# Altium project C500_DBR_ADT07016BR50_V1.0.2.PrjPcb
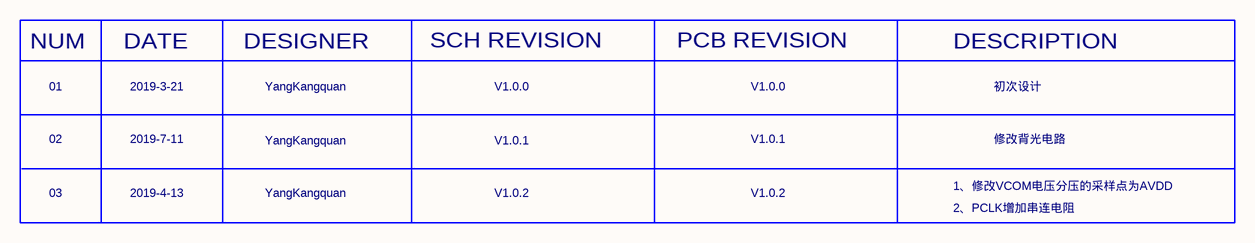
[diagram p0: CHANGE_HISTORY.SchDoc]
3 sheets, 129 parts. Net scope: flat (ports and power ports of the same name join across sheets).
Sheets:
  CHANGE_HISTORY.SchDoc
  POWER.SchDoc
  CONNECT.SchDoc

## Sheet CHANGE_HISTORY.SchDoc: C500_DBR_ADT07016BR50
size A3; Revision: V1.0.2; SheetNumber: 1; SheetTotal: 3

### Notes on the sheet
- NUM
- DATE
- DESIGNER
- SCH REVISION
- PCB REVISION
- DESCRIPTION
- 01
- 2019-3-21
- YangKangquan
- V1.0.0
- 初次设计
- 02
- 03
- 2019-7-11
- 2019-4-13
- V1.0.1
- V1.0.2
- 1、修改VCOM电压分压的采样点为AVDD
- 修改背光电路
- 2、PCLK增加串连电阻

## Sheet POWER.SchDoc: C500_DBR_ADT07016BR50
size A3; Revision: V1.0.2; SheetNumber: 2; SheetTotal: 3
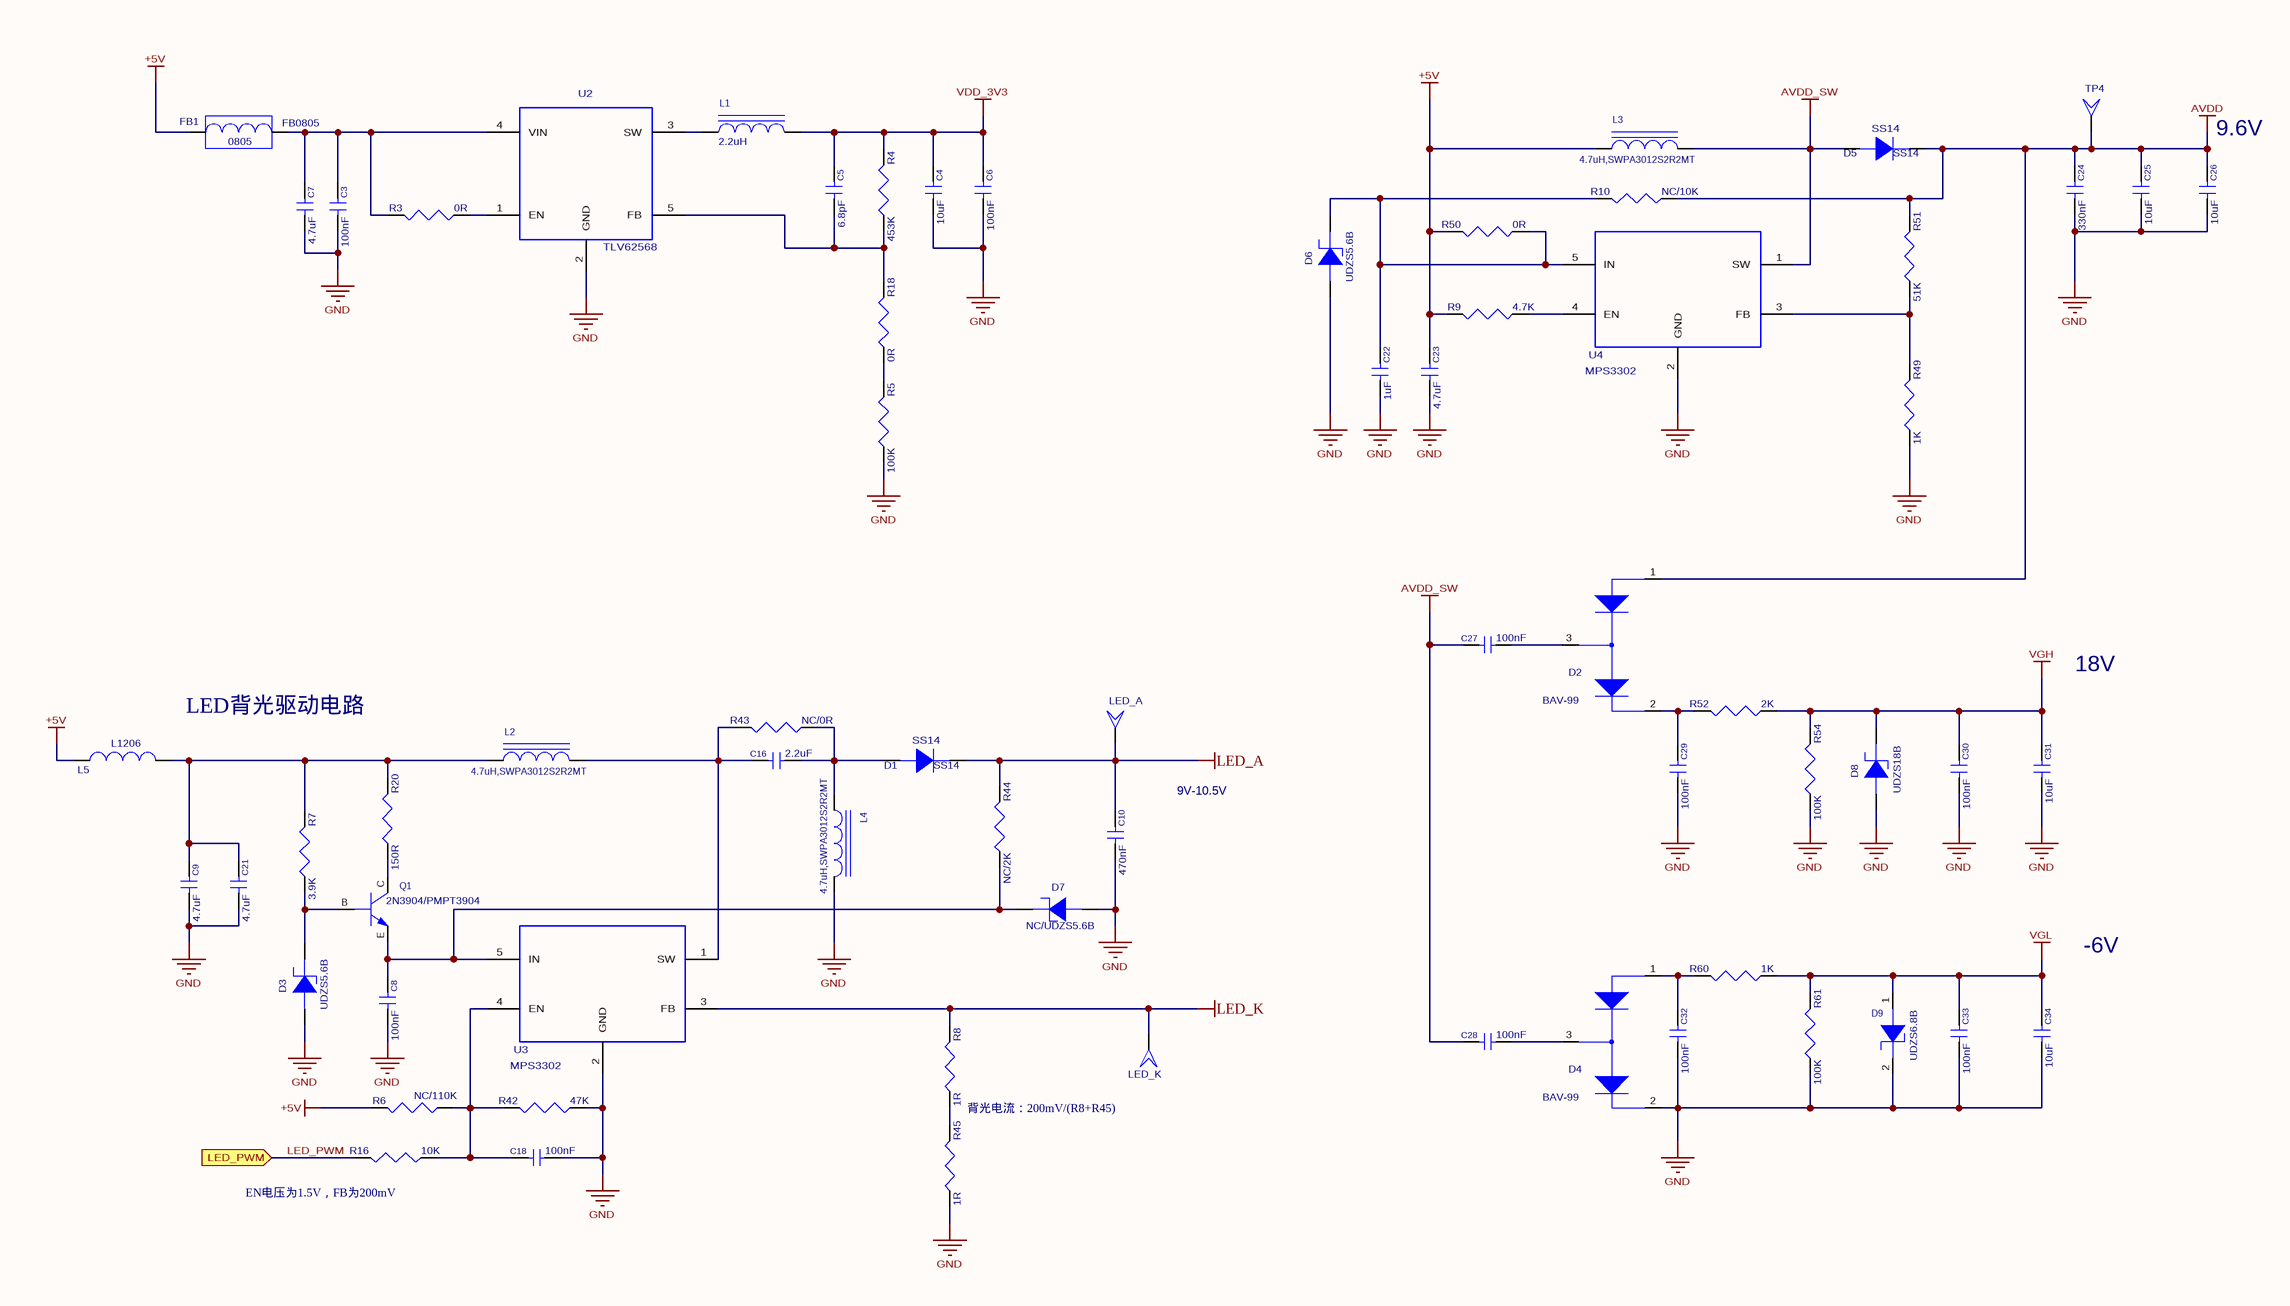
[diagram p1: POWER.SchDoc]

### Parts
C3  100nF  [C0603]
C4  10uF  [C0603]
C5  6.8pF  [C0603]
C6  100nF  [C0603]
C7  4.7uF  [C0603]
C8  100nF  [C0603]
C9  4.7uF  [C0603]
C10  470nF  [C0603]
C16  2.2uF  [C0603]
C18  100nF  [C0603]
C21  4.7uF  [C0603]
C22  1uF  [C0603]
C23  4.7uF  [C0603]
C24  330nF  [C0603]
C25  10uF  [C0603]
C26  10uF  [C0603]
C27  100nF  [C0603]
C28  100nF  [C0603]
C29  100nF  [C0603]
C30  100nF  [C0603]
C31  10uF  [C0603]
C32  100nF  [C0603]
C33  100nF  [C0603]
C34  10uF  [C0603]
D1  SS14  [SS14]
D2  BAV-99  [BAV-99_SOT23_123]
D3  UDZS5.6B  [UDZS6.8B]
D4  BAV-99  [BAV-99_SOT23_123]
D5  SS14  [SS14]
D6  UDZS5.6B  [UDZS6.8B]
D7  NC/UDZS5.6B  [UDZS6.8B]
D8  UDZS18B  [UDZS6.8B]
D9  UDZS6.8B  [UDZS6.8B]
FB1  FB0805  [FB0805]
L1  2.2uH  [L_SWPA3012_3X3MM]
L2  value 4.7uH,SWPA3012S2R2MT  [L_SWPA3012_3X3MM]  (hidden comment: 4.7uH,SWPA3012S4R7MT)
L3  value 4.7uH,SWPA3012S2R2MT  [L_SWPA3012_3X3MM]  (hidden comment: 4.7uH,SWPA3012S4R7MT)
L4  value 4.7uH,SWPA3012S2R2MT  [L_SWPA3012_3X3MM]  (hidden comment: 4.7uH,SWPA3012S4R7MT)
L5  L1206  [L1206]
LED_A  TP40  [TP40]  (value not drawn)
LED_K  TP40  [TP40]  (value not drawn)
Q1  value 2N3904/PMPT3904  [2N3904/PMBT3904]  (hidden comment: 2N3904/PMBT3904)
R3  0R  [R0603]
R4  453K  [R0603]
R5  100K  [R0603]
R6  NC/110K  [R0603]
R7  3.9K  [R0603]
R8  1R  [R0603]
R9  4.7K  [R0603]
R10  NC/10K  [R0603]
R16  10K  [R0603]
R18  0R  [R0603]
R20  150R  [R0603]
R42  47K  [R0603]
R43  NC/0R  [R0603]
R44  NC/2K  [R0603]
R45  1R  [R0603]
R49  1K  [R0603]
R50  0R  [R0603]
R51  51K  [R0603]
R52  2K  [R0603]
R54  100K  [R0603]
R60  1K  [R0603]
R61  100K  [R0603]
TP4  TP40  [TP40]  (value not drawn)
U2  TLV62568  [PAM2312_SOT23_5]
U3  MPS3302  [MPS3302_SOT23-5]
U4  MPS3302  [MPS3302_SOT23-5]

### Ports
LED_PWM (in)

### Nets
+5V: C23.1 FB1.1 L3.1 L5.1 R6.2 R9.2 R50.2
AVDD: C24.1 C25.1 C26.1 D2.1(GND) D5.K R10.1 R51.2 TP4.1
AVDD_SW: C27.1 C28.1 D5.A L3.2 U4.1(SW)
GND: C3.2 C4.2 C6.2 C7.2 C8.2 C9.2 C10.2 C18.2 C21.2 C22.2 C23.2 C24.2 C25.2 C26.2 C29.2 C30.2 C31.2 C32.2 C33.2 C34.2 D3.1(A) D4.2(VDD) D6.1(A) D7.1(A) D8.1(A) D9.2(K) L4.2 R5.1 R42.1 R45.1 R49.1 R54.1 R61.1 U2.2(GND) U3.2(GND) U4.2(GND)
LED_A: C10.1 D1.K LED_A.1 R44.2
LED_K: LED_K.1 R8.2 U3.3(FB)
VDD_3V3: C4.1 C5.1 C6.1 L1.2 R4.2
VGH: C30.1 C31.1 D8.2(K) R52.1 R54.2
VGL: C33.1 C34.1 D9.1(A) R60.1 R61.2
LED_PWM: R16.2 ; port LED_PWM
NetC3_1: C3.1 C7.1 FB1.2 R3.2 U2.4(VIN)
NetC5_2: C5.2 R4.1 R18.2 U2.5(FB)
NetC8_1: C8.1 D7.2(K) Q1.E R44.1 U3.5(IN)
NetC9_1: C9.1 C21.1 L2.1 L5.2 R7.2 R20.2
NetC16_1: C16.1 L2.2 R43.2 U3.1(SW)
NetC16_2: C16.2 D1.A L4.1 R43.1
NetC18_1: C18.1 R6.1 R16.1 R42.2 U3.4(EN)
NetC22_1: C22.1 D6.2(K) R10.2 R50.1 U4.5(IN)
NetC27_2: C27.2 D2.3(SIGNAL)
NetC28_2: C28.2 D4.3(SIGNAL)
NetC29_1: C29.1 D2.2(VDD) R52.2
NetC32_1: C32.1 D4.1(GND) R60.2
NetD3_2: D3.2(K) Q1.B R7.1
NetL1_1: L1.1 U2.3(SW)
NetQ1_C: Q1.C R20.1
NetR3_1: R3.1 U2.1(EN)
NetR5_2: R5.2 R18.1
NetR8_1: R8.1 R45.2
NetR9_1: R9.1 U4.4(EN)
NetR49_2: R49.2 R51.1 U4.3(FB)

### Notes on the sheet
- (near C26) 9.6V
- 18V
- (near L5) LED背光驱动电路
- 9V-10.5V
- -6V
- 背光电流：200mV/(R8+R45)
- (near R16) EN电压为1.5V，FB为200mV

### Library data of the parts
C3 C6 C8 C18 C27-C30 C32 C33 = CC0301040XX: C/C,100nF,25V,+/-5%,0603; Catalog: 陶瓷电容
C4 = CC0301064XX: C/C,10uF,6.3V,+/-20%,0603; Catalog: 陶瓷电容
C5 = CC0306R80XX: C/C,6.8pF,50V,+/-0.25pF,0603; Catalog: 陶瓷电容
C7 C9 C21 C23 = CC0304752XX: C/C,4.7uF,10V +/-10%,0603; Catalog: 陶瓷电容
C10 = CC0304742XX: C/C,470nF,25V,+/-10%,0603; Catalog: 陶瓷电容
C16 = CC0302251XX: C/C,2.2uF,25V,+/-5%,,0603; Catalog: 陶瓷电容
C22 = CC0301055XX: C/C,1uF,16V,+/-10%,0603; Catalog: 陶瓷电容
C24 = CC0303340XX: C/C,330nF,50V,+/-5%,0603; Catalog: 陶瓷电容
C25 C26 C31 C34 = CC0301060XX: C/C,10uF,25V,+/-5%,0603; Catalog: 陶瓷电容
D1 D5 = DDD0SCH00XX: SS14 DO-214AC 肖特基二极管; Catalog: 二极管
D2 D4 = DD21SSD00XX: Small signal Diodes,onsemi,BAV99LT1G,SOT23; Catalog: 二极管
D3 D6 = DD23ZEN03XX: Zener Diode,UDZS5.6B,5.6V,S0D-323; Catalog: 二极管
D7 = DD23ZEN03XX: Zener Diode,UDZS5.6B,5.6V,S0D-323; Remark: NC; Catalog: 二极管
D8 = DD23ZEN04XX: 稳压管：Zener Diode,UDZS18B,18V,S0D-323; PCB DECAL: UDZS5.6B; Catalog: 二极管
D9 = DD33ZEN68XX: Zener Diode,UDZS6.8B,6.8V,S0D-323; Catalog: 稳压管
FB1 = BE0503010XX: BEAD,PZ2012U301-1R5TF,300R,100MHz,0805; Catalog: 贴片磁珠
L1 = WL1C02R20XX: 2.2uH,SWPA3012S2R2NT; SOURCE_PATH: E:\工作目录\ORCAD原理图库\ORCAD元件库\磁珠&电感.OLB; Catalog: 贴片电感
L2-L4 = WL1C04R70XX: Part Number_AK: WL1C02R20XX; SOURCE_PATH: E:\工作目录\ORCAD原理图库\ORCAD元件库\磁珠&电感.OLB; Catalog: 贴片电感
L5 = BE0606010XX: PZ3216D601_L1206,PZ3216D601-1R5TF; SOURCE_PATH: E:\工作目录\ORCAD原理图库\ORCAD元件库\磁珠&电感.OLB; Catalog: 贴片磁珠
Q1 = TR05NGN00XX: 2N3904/PMBT3904,SOT-23,NPN,GP; PCB DECAL: 2N3904/PMBT3904_SOT23_BCE_NPN; Catalog: 三极管
R3 R18 R43 R50 = CR0300000XX: Res,0R,1/10W,+/-5%,0603; Catalog: 贴片电阻
R4 = CR0345330XX: Res,453K,1/16W,+/-1%,0603; Catalog: 贴片电阻
R5 R54 R61 = CR0310030XX: Res,100K,1/10W,+/-1%,0603; Catalog: 贴片电阻
R6 = CR0311030XX: Res,110K,1/10W,+/-1%,0603; Catalog: 贴片电阻
R7 = CR0339010XX: Res,3.9K,1/10W,+/-1%,0603; Catalog: 贴片电阻
R8 R45 = CR031R000XX: Res,1R,1/10W,+/-1%,0603; Catalog: 贴片电阻
R9 = CR0304720XX: Res,4.7K,1/10W,+/-5%,0603; Catalog: 贴片电阻
R10 R16 = CR0310020XX: Res,10K,1/10W,+/-1%,0603; Remark: NC; Catalog: 贴片电阻
R20 = CR0315000XX: Res,150R,1/10W,+/-1%,0603; Catalog: 贴片电阻
R42 = CR0347020XX: Res,47K,1/10W,+/-1%,0603; Catalog: 贴片电阻
R44 R52 = CR0302020XX: Res,2K,1/10W,+/-5%,0603; Catalog: 贴片电阻
R49 R60 = CR0301020XX: Res,1K,1/10W,+/-5%,0603; Catalog: 贴片电阻
R51 = CR0305131XX: Res,51K,1/10W,+/-1%,0603; Catalog: 贴片电阻
U2 = JCSOTPW23XX: PowerIC , TI, TLV62568DBV, SOT23-5; PCB DECAL: TLV62568_SOT23-5; Catalog: 集成电路
U3 U4 = JCSOTDR00XX: IC MP3302，LCD Drives LED，TSOT23-5; Catalog: 集成电路

## Sheet CONNECT.SchDoc: C500_DBR_ADT07016BR50
size A3; Revision: V1.0.2; SheetNumber: 3; SheetTotal: 3
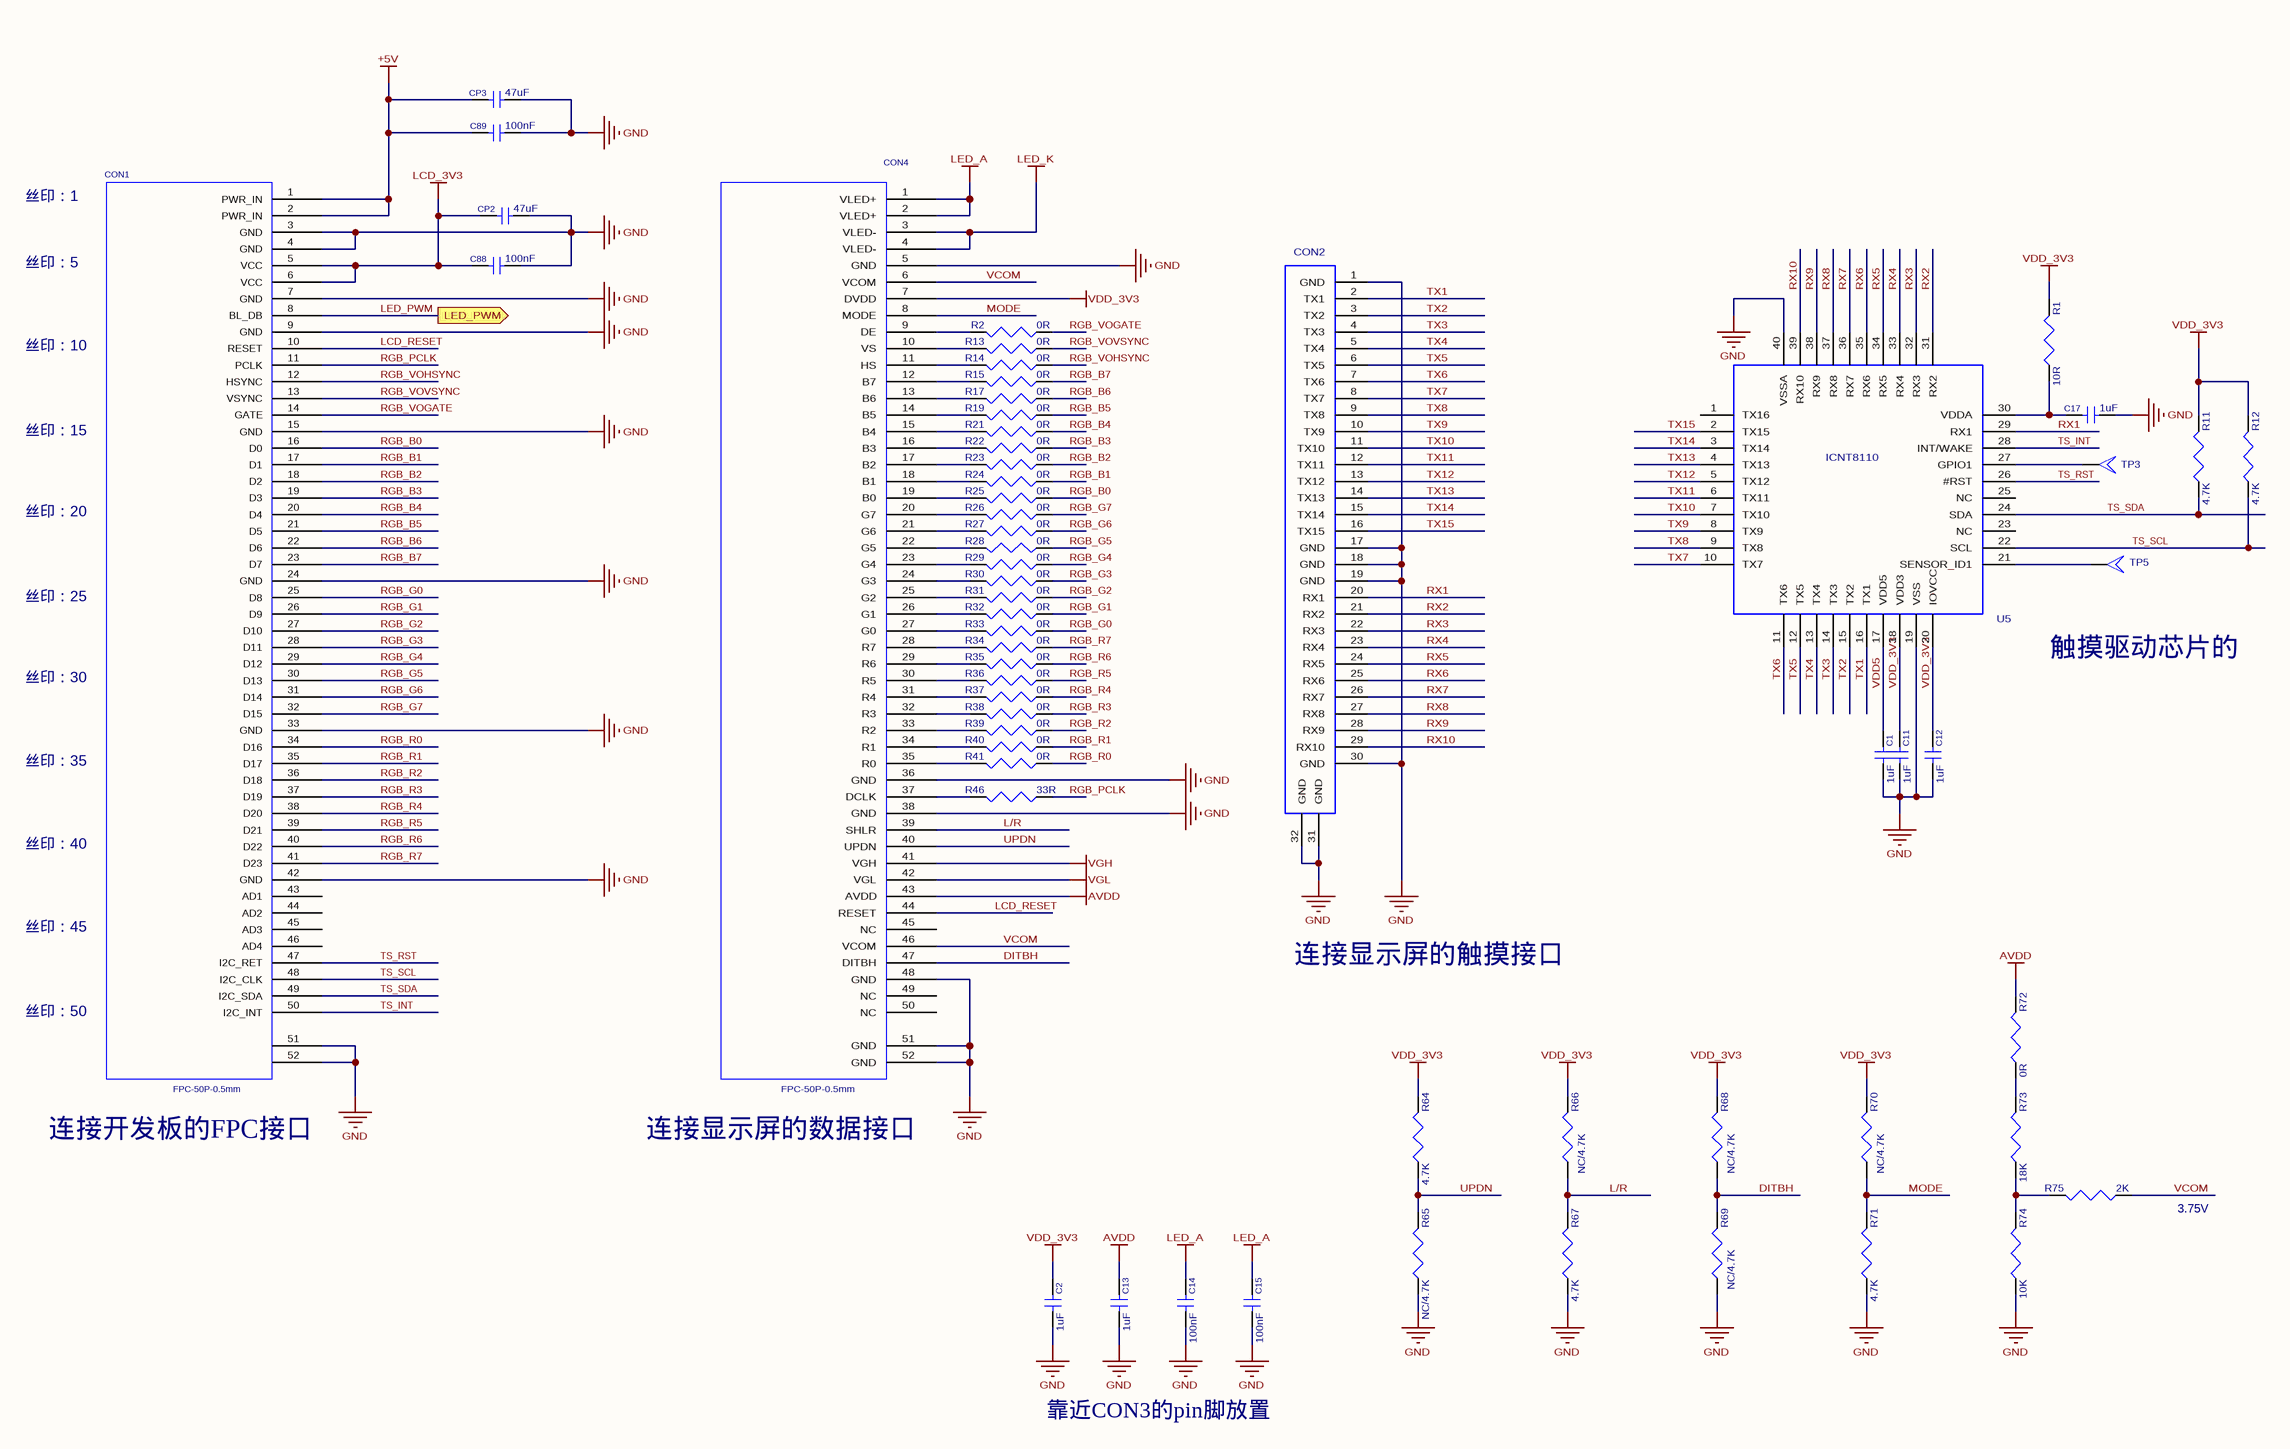
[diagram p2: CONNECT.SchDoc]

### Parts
C1  1uF  [C0603]
C2  1uF  [C0603]
C11  1uF  [C0603]
C12  1uF  [C0603]
C13  1uF  [C0603]
C14  100nF  [C0603]
C15  100nF  [C0603]
C17  1uF  [C0603]
C88  100nF  [C0603]
C89  100nF  [C0603]
CON1  FPC-50P-0.5MM  [FPC-50P-0.5MM]
CON2  CON30_FPC_0.5MM  [CON30_0MM5]  (value not drawn)
CON4  value FPC-50P-0.5mm  [FPC_LCD_50P_0.5mm]  (hidden comment: FPC_LCD_50P_0.5mm)
CP2  47uF  [C1210]
CP3  47uF  [C1210]
R1  10R  [R0603]
R2  0R  [R0603]
R11  4.7K  [R0603]
R12  4.7K  [R0603]
R13  0R  [R0603]
R14  0R  [R0603]
R15  0R  [R0603]
R17  0R  [R0603]
R19  0R  [R0603]
R21  0R  [R0603]
R22  0R  [R0603]
R23  0R  [R0603]
R24  0R  [R0603]
R25  0R  [R0603]
R26  0R  [R0603]
R27  0R  [R0603]
R28  0R  [R0603]
R29  0R  [R0603]
R30  0R  [R0603]
R31  0R  [R0603]
R32  0R  [R0603]
R33  0R  [R0603]
R34  0R  [R0603]
R35  0R  [R0603]
R36  0R  [R0603]
R37  0R  [R0603]
R38  0R  [R0603]
R39  0R  [R0603]
R40  0R  [R0603]
R41  0R  [R0603]
R46  33R  [R0603]
R64  4.7K  [R0603]
R65  NC/4.7K  [R0603]
R66  NC/4.7K  [R0603]
R67  4.7K  [R0603]
R68  NC/4.7K  [R0603]
R69  NC/4.7K  [R0603]
R70  NC/4.7K  [R0603]
R71  4.7K  [R0603]
R72  0R  [R0603]
R73  18K  [R0603]
R74  10K  [R0603]
R75  2K  [R0603]
TP3  TP40  [TP40]  (value not drawn)
TP5  TP40  [TP40]  (value not drawn)
U5  ICNT8110  [QFN40_0MM5_5X5MM]  (value not drawn)

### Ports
LED_PWM (out)

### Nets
+5V: C89.1 CON1.1(PWR_IN) CON1.2(PWR_IN) CP3.1
AVDD: C13.1 CON4.43(AVDD) R72.2
GND: C1.2 C2.2 C11.2 C12.2 C13.2 C14.2 C15.2 C17.2 C88.2 C89.2 CON1.3(GND) CON1.4(GND) CON1.7(GND) CON1.9(GND) CON1.15(GND) CON1.24(GND) CON1.33(GND) CON1.42(GND) CON1.51 CON1.52 CON2.1(GND) CON2.17(GND) CON2.18(GND) CON2.19(GND) CON2.30(GND) CON2.31(GND) CON2.32(GND) CON4.5(GND) CON4.36(GND) CON4.38(GND) CON4.48(GND) CON4.51(GND) CON4.52(GND) CP2.2 CP3.2 R65.1 R67.1 R69.1 R71.1 R74.1 U5.19(VSS) U5.40(VSSA)
LCD_3V3: C88.1 CON1.5(VCC) CON1.6(VCC) CP2.1
LED_A: C14.1 C15.1 CON4.1(VLED+) CON4.2(VLED+)
LED_K: CON4.3(VLED-) CON4.4(VLED-)
VDD_3V3: C2.1 C11.1 C12.1 CON4.7(DVDD) R1.2 R11.2 R12.2 R64.2 R66.2 R68.2 R70.2 U5.18(VDD3) U5.20(IOVCC)
VGH: CON4.41(VGH)
VGL: CON4.42(VGL)
DITBH: CON4.47(DITBH) R68.1 R69.2
L/R: CON4.39(SHLR) R66.1 R67.2
LCD_RESET: CON1.10(RESET) CON4.44(RESET)
LED_PWM: CON1.8(BL_DB) ; port LED_PWM
MODE: CON4.8(MODE) R70.1 R71.2
RGB_B0: CON1.16(D0) R25.1
RGB_B1: CON1.17(D1) R24.1
RGB_B2: CON1.18(D2) R23.1
RGB_B3: CON1.19(D3) R22.1
RGB_B4: CON1.20(D4) R21.1
RGB_B5: CON1.21(D5) R19.1
RGB_B6: CON1.22(D6) R17.1
RGB_B7: CON1.23(D7) R15.1
RGB_G0: CON1.25(D8) R33.1
RGB_G1: CON1.26(D9) R32.1
RGB_G2: CON1.27(D10) R31.1
RGB_G3: CON1.28(D11) R30.1
RGB_G4: CON1.29(D12) R29.1
RGB_G5: CON1.30(D13) R28.1
RGB_G6: CON1.31(D14) R27.1
RGB_G7: CON1.32(D15) R26.1
RGB_PCLK: CON1.11(PCLK) R46.1
RGB_R0: CON1.34(D16) R41.1
RGB_R1: CON1.35(D17) R40.1
RGB_R2: CON1.36(D18) R39.1
RGB_R3: CON1.37(D19) R38.1
RGB_R4: CON1.38(D20) R37.1
RGB_R5: CON1.39(D21) R36.1
RGB_R6: CON1.40(D22) R35.1
RGB_R7: CON1.41(D23) R34.1
RGB_VOGATE: CON1.14(GATE) R2.1
RGB_VOHSYNC: CON1.12(HSYNC) R14.1
RGB_VOVSYNC: CON1.13(VSYNC) R13.1
RX1: CON2.20(RX1) U5.29(RX1)
RX2: CON2.21(RX2) U5.31(RX2)
RX3: CON2.22(RX3) U5.32(RX3)
RX4: CON2.23(RX4) U5.33(RX4)
RX5: CON2.24(RX5) U5.34(RX5)
RX6: CON2.25(RX6) U5.35(RX6)
RX7: CON2.26(RX7) U5.36(RX7)
RX8: CON2.27(RX8) U5.37(RX8)
RX9: CON2.28(RX9) U5.38(RX9)
RX10: CON2.29(RX10) U5.39(RX10)
TS_INT: CON1.50(I2C_INT) U5.28(INT/WAKE)
TS_RST: CON1.47(I2C_RET) U5.26(#RST)
TS_SCL: CON1.48(I2C_CLK) R12.1 U5.22(SCL)
TS_SDA: CON1.49(I2C_SDA) R11.1 U5.24(SDA)
TX1: CON2.2(TX1) U5.16(TX1)
TX2: CON2.3(TX2) U5.15(TX2)
TX3: CON2.4(TX3) U5.14(TX3)
TX4: CON2.5(TX4) U5.13(TX4)
TX5: CON2.6(TX5) U5.12(TX5)
TX6: CON2.7(TX6) U5.11(TX6)
TX7: CON2.8(TX7) U5.10(TX7)
TX8: CON2.9(TX8) U5.9(TX8)
TX9: CON2.10(TX9) U5.8(TX9)
TX10: CON2.11(TX10) U5.7(TX10)
TX11: CON2.12(TX11) U5.6(TX11)
TX12: CON2.13(TX12) U5.5(TX12)
TX13: CON2.14(TX13) U5.4(TX13)
TX14: CON2.15(TX14) U5.3(TX14)
TX15: CON2.16(TX15) U5.2(TX15)
UPDN: CON4.40(UPDN) R64.1 R65.2
VCOM: CON4.6(VCOM) CON4.46(VCOM) R75.1
VDD5: C1.1 U5.17(VDD5)
NetC17_1: C17.1 R1.1 U5.30(VDDA)
NetCON4_9: CON4.9(DE) R2.2
NetCON4_10: CON4.10(VS) R13.2
NetCON4_11: CON4.11(HS) R14.2
NetCON4_12: CON4.12(B7) R15.2
NetCON4_13: CON4.13(B6) R17.2
NetCON4_14: CON4.14(B5) R19.2
NetCON4_15: CON4.15(B4) R21.2
NetCON4_16: CON4.16(B3) R22.2
NetCON4_17: CON4.17(B2) R23.2
NetCON4_18: CON4.18(B1) R24.2
NetCON4_19: CON4.19(B0) R25.2
NetCON4_20: CON4.20(G7) R26.2
NetCON4_21: CON4.21(G6) R27.2
NetCON4_22: CON4.22(G5) R28.2
NetCON4_23: CON4.23(G4) R29.2
NetCON4_24: CON4.24(G3) R30.2
NetCON4_25: CON4.25(G2) R31.2
NetCON4_26: CON4.26(G1) R32.2
NetCON4_27: CON4.27(G0) R33.2
NetCON4_28: CON4.28(R7) R34.2
NetCON4_29: CON4.29(R6) R35.2
NetCON4_30: CON4.30(R5) R36.2
NetCON4_31: CON4.31(R4) R37.2
NetCON4_32: CON4.32(R3) R38.2
NetCON4_33: CON4.33(R2) R39.2
NetCON4_34: CON4.34(R1) R40.2
NetCON4_35: CON4.35(R0) R41.2
NetCON4_37: CON4.37(DCLK) R46.2
NetR72_1: R72.1 R73.2
NetR73_1: R73.1 R74.2 R75.2
NetTP3_1: TP3.1 U5.27(GPIO1)
NetTP5_1: TP5.1 U5.21(SENSOR_ID1)

Not connected (* = marked no-connect by the designer): CON1 43(AD1) 44(AD2) 45(AD3) 46(AD4); CON4 45(NC) 49(NC) 50(NC); U5 1(TX16) 23(NC) 25(NC)

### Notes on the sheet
- 丝印：1
- 丝印：5
- 丝印：10
- 丝印：15
- 丝印：20
- 丝印：25
- 丝印：30
- 触摸驱动芯片的
- 丝印：35
- 丝印：40
- 丝印：45
- 连接显示屏的触摸接口
- 丝印：50
- 连接开发板的FPC接口
- 连接显示屏的数据接口
- (near R75) 3.75V
- 靠近CON3的pin脚放置

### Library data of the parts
C1 C2 C11-C13 C17 = CC0301055XX: C/C,1uF,16V,+/-10%,0603; Catalog: 陶瓷电容
C14 C15 C88 C89 = CC0301040XX: C/C,100nF,25V,+/-5%,0603; Catalog: 陶瓷电容
CON1 = CNFPF5001XX: 连接器 FPC连接器，50P，0.5mm，翻盖式，H=2mm; ROOM: lcd1; Source Path: D:\MAGIC\SCHEMATICS\MAGIC_DAUGHTERBD_EVT_V1.DSN; PCB DECAL: CON50_0MM5; Catalog: Connector
CON2 = CNFPF3002XX: 连接器 FPC连接器 FPC0.5mm -30P H1.0mm 前插后掀；; Catalog: Connector
CON4 = CNFPC5000XX: FPC连接器 FPC0.5mm -50P H1.0mm 前插后掀；; ROOM: lcd1; Source Path: D:\MAGIC\SCHEMATICS\MAGIC_DAUGHTERBD_EVT_V1.DSN; PCB DECAL: SAT070AT50D18Y0_LCD; Catalog: Connector
CP2 CP3 = TC1004761XX: T/C,47uF,10V,+/-10%,1210; Catalog: 陶瓷电容
R1 = CR0301000XX: Res,10R,1/10W,+/-5%,0603; Catalog: 贴片电阻
R2 R13-R15 R17 R19 R21-R41 R72 = CR0300000XX: Res,0R,1/10W,+/-5%,0603; Catalog: 贴片电阻
R11 R12 R64 R67 R71 = CR0304720XX: Res,4.7K,1/10W,+/-5%,0603; Catalog: 贴片电阻
R46 = CR0333R00XX: Res,33R,1/10W,+/-1%,0603; Catalog: 贴片电阻
R65 R66 R68-R70 = CR0304720XX: Res,4.7K,1/10W,+/-5%,0603; Remark: NC; Catalog: 贴片电阻
R73 = CR0318020XX: Res,18K,1/10W,+/-1%,0603; Catalog: 贴片电阻
R74 = CR0310020XX: as R10 on sheet POWER
R75 = CR0302020XX: Res,2K,1/10W,+/-5%,0603; Catalog: 贴片电阻
U5 = JCQFNVP01XX: Capacitive Touch Sensor Controller，ICNT8110 QFN40_5*5; Catalog: 集成电路

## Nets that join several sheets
+5V: POWER (7 pins), CONNECT (C89.1 CON1.1 CON1.2 CP3.1)
AVDD: POWER (8 pins), CONNECT (C13.1 CON4.43 R72.2)
GND: POWER (36 pins), CONNECT (42 pins)
LED_A: POWER (C10.1 D1.K LED_A.1 R44.2), CONNECT (C14.1 C15.1 CON4.1 CON4.2)
LED_K: POWER (LED_K.1 R8.2 U3.3), CONNECT (CON4.3 CON4.4)
VDD_3V3: POWER (5 pins), CONNECT (13 pins)
VGH: POWER (5 pins), CONNECT (CON4.41)
VGL: POWER (5 pins), CONNECT (CON4.42)
LED_PWM: POWER (R16.2), CONNECT (CON1.8)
